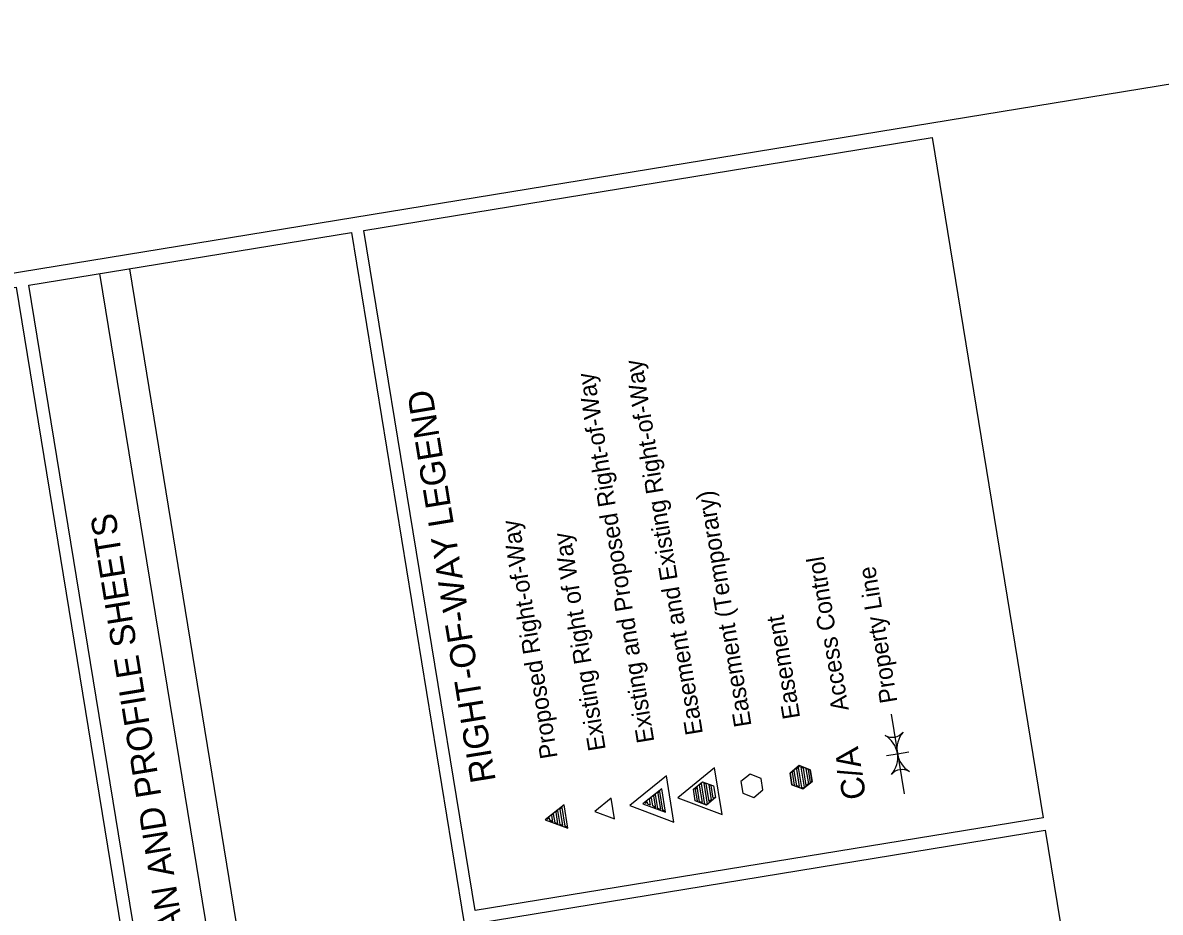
# Model space of a CAD drawing. Extents: x 21481360 to 21488265, y 8074918 to 8087833.
# Drawn here: x 21482042 to 21483023, y 8087066 to 8087833 of the extents above; entities that cross this region are included whole.
import ezdxf

# ---------------------------------------------------------------- set-up
doc = ezdxf.new("R2010")
doc.units = 0
for name, color, linetype in [('brgDimensionLines', 7, 'Continuous'), ('Default', 7, 'Continuous'), ('EXT_EW', 7, 'Continuous'), ('EXT_SH', 7, 'Continuous'), ('Roadways', 7, 'Continuous'), ('SheetBorder', 7, 'Continuous'), ('SheetGridMajor', 7, 'Continuous'), ('SheetText', 7, 'Continuous'), ('SurControl', 7, 'Continuous'), ('SurTopOfWater', 7, 'Continuous')]:
    doc.layers.add(name, color=color, linetype=linetype)

msp = doc.modelspace()

# ---------------------------------------------------------------- linework, layer by layer
at = {"layer": 'brgDimensionLines'}
msp.add_lwpolyline([(21482545.78, 8087154.73), (21482545.76, 8087154.75)], dxfattribs=at)
at = {"layer": 'Default'}
msp.add_lwpolyline([(21481866.15, 8084413.58), (21481360.5, 8087507.53), (21483354.05, 8087833.34), (21483859.7, 8084739.39)], close=True, dxfattribs=at)
at = {"layer": 'EXT_EW'}
for points in [[(21482645.14, 8087150.46), (21482638.59, 8087190.57), (21482607.13, 8087164.84)], [(21482603.67, 8087143.68), (21482597.12, 8087183.79), (21482565.66, 8087158.06)], [(21482552.47, 8087146.56), (21482549.52, 8087164.6), (21482535.36, 8087153.02)]]:
    msp.add_lwpolyline(points, close=True, dxfattribs=at)
at = {"layer": 'Roadways'}
for p, q in [((21482327.61, 8086436.88), (21482134.05, 8087621.17)), ((21482301.95, 8086432.69), (21482108.4, 8087616.97))]:
    msp.add_line(p, q, dxfattribs=at)
at = {"layer": 'SheetBorder'}
msp.add_lwpolyline([(21482722.84, 8087178.94), (21482721.2, 8087188.97), (21482711.7, 8087192.56), (21482703.84, 8087186.13), (21482705.48, 8087176.1), (21482714.98, 8087172.51)], close=True, dxfattribs=at)
at = {"layer": 'SheetText'}
for points in [[(21482722.84, 8087178.94), (21482714.98, 8087172.51), (21482705.48, 8087176.1), (21482703.84, 8087186.13), (21482711.7, 8087192.56), (21482721.2, 8087188.97), (21482722.84, 8087178.94), (21482721.52, 8087178.06), (21482719.72, 8087189.09), (21482717.55, 8087189.77), (21482719.68, 8087176.73), (21482717.84, 8087175.4), (21482715.38, 8087190.44), (21482713.21, 8087191.12), (21482716, 8087174.07), (21482715.16, 8087172.91), (21482714, 8087173.74), (21482711.21, 8087190.79), (21482712.05, 8087191.96), (21482709.37, 8087189.46), (21482711.82, 8087174.42), (21482709.66, 8087175.09), (21482707.53, 8087188.13), (21482705.68, 8087186.8), (21482707.49, 8087175.77)], [(21482639.49, 8087164.95), (21482631.63, 8087158.52), (21482622.12, 8087162.11), (21482620.49, 8087172.14), (21482628.35, 8087178.57), (21482637.85, 8087174.98), (21482639.49, 8087164.95), (21482637.64, 8087164.35), (21482635.84, 8087175.38), (21482633.67, 8087176.06), (21482635.8, 8087163.02), (21482633.95, 8087161.69), (21482631.5, 8087176.73), (21482629.33, 8087177.41), (21482632.28, 8087159.36), (21482630.27, 8087159.03), (21482627.32, 8087177.08), (21482625.48, 8087175.75), (21482627.94, 8087160.71), (21482625.77, 8087161.38), (21482623.64, 8087174.42), (21482621.96, 8087172.09), (21482623.6, 8087162.06)], [(21482596.51, 8087152.48), (21482593.24, 8087172.54), (21482576.83, 8087159.56), (21482596.51, 8087152.48), (21482594.18, 8087154.16), (21482591.56, 8087170.21), (21482589.72, 8087168.88), (21482592.01, 8087154.84), (21482589.84, 8087155.51), (21482587.88, 8087167.55), (21482586.03, 8087166.21), (21482587.67, 8087156.19), (21482585.34, 8087157.87), (21482584.19, 8087164.88), (21482582.35, 8087163.55), (21482583.17, 8087158.54), (21482581, 8087159.22), (21482580.67, 8087161.22), (21482578.83, 8087159.89)], [(21482512.1, 8087138.69), (21482508.82, 8087158.75), (21482492.41, 8087145.77), (21482512.1, 8087138.69), (21482509.77, 8087140.37), (21482507.14, 8087156.41), (21482505.3, 8087155.08), (21482507.6, 8087141.04), (21482505.43, 8087141.72), (21482503.46, 8087153.75), (21482501.62, 8087152.42), (21482503.26, 8087142.39), (21482501.09, 8087143.07), (21482499.78, 8087151.09), (21482497.94, 8087149.76), (21482498.92, 8087143.74), (21482496.59, 8087145.42), (21482496.26, 8087147.43), (21482494.42, 8087146.1)]]:
    msp.add_lwpolyline(points, dxfattribs=at)
msp.add_lwpolyline([(21482680.5, 8087171.53), (21482678.87, 8087181.56), (21482669.36, 8087185.16), (21482661.5, 8087178.72), (21482663.14, 8087168.7), (21482672.64, 8087165.1)], close=True, dxfattribs=at)
at = {"layer": 'SurControl'}
for p, q in [((21482046.96, 8087606.93), (21482325.51, 8087652.46)), ((21482325.51, 8087652.46), (21482518.82, 8086468.13)), ((21482240.51, 8086422.65), (21482046.96, 8087606.93))]:
    msp.add_line(p, q, dxfattribs=at)
for points in [[(21482432.01, 8087067.48), (21482336.12, 8087654.19), (21482826.38, 8087734.32), (21482922.27, 8087147.6), (21482432.01, 8087067.48)], [(21482529.67, 8086469.9), (21482433.79, 8087056.62), (21482924.04, 8087136.74), (21483019.93, 8086550.03), (21482529.67, 8086469.9)]]:
    msp.add_lwpolyline(points, dxfattribs=at)
msp.add_lwpolyline([(21481566.94, 8086312.56), (21481373.39, 8087496.85), (21482036.1, 8087605.16), (21482229.65, 8086420.87)], close=True, dxfattribs=at)
at = {"layer": 'SurTopOfWater'}
for p, q in [((21482791, 8087236.81), (21482802.2, 8087168.28)), ((21482796.6, 8087202.55), (21482786.98, 8087200.98)), ((21482796.49, 8087202.75), (21482796.49, 8087202.75)), ((21482806.22, 8087204.12), (21482796.6, 8087202.55)), ((21482796.6, 8087202.55), (21482796.6, 8087202.55))]:
    msp.add_line(p, q, dxfattribs=at)
for centre, radius, start, end in [((21482791.97, 8087229.23), 12.19, 240.26162, 320.11157), ((21482774.42, 8087199.49), 22.34, 319.25809, 59.02928), ((21482819.1, 8087206.8), 23.01, 140.58433, 237.70642), ((21482800.42, 8087177.35), 11.81, 57.74196, 140.21653)]:
    msp.add_arc(centre, radius, start, end, dxfattribs=at)

# ---------------------------------------------------------------- texts
at = {"layer": 'EXT_SH'}
for s, height, p in [('Easement and Existing Right-of-Way', 15, (21482628.73, 8087220.21)), ('Existing and Proposed Right-of-Way', 15, (21482586.79, 8087213.36)), ('RIGHT-OF-WAY LEGEND', 21.6667, (21482449.99, 8087179.62)), ('Easement (Temporary)', 15, (21482670.67, 8087227.07)), ('PROFILE VIEW COLOR LEGEND OF PLAN AND PROFILE SHEETS', 21.6667, (21482266.86, 8086521.58)), ('Proposed Right-of-Way', 15, (21482503.37, 8087199.73)), ('Existing Right of Way', 15, (21482544.84, 8087206.5)), ('Access Control', 15, (21482754.56, 8087240.78)), ('Property Line', 15, (21482796.5, 8087247.63)), ('Easement', 15, (21482712.62, 8087233.92))]:
    msp.add_text(s, height=height, rotation=99.28189, dxfattribs=at).set_placement(p)
at = {"layer": 'SheetGridMajor'}
msp.add_text('C/A', height=20.32, rotation=99.28189, dxfattribs=at).set_placement((21482769.65, 8087164.94))

doc.saveas('drawing.dxf')
